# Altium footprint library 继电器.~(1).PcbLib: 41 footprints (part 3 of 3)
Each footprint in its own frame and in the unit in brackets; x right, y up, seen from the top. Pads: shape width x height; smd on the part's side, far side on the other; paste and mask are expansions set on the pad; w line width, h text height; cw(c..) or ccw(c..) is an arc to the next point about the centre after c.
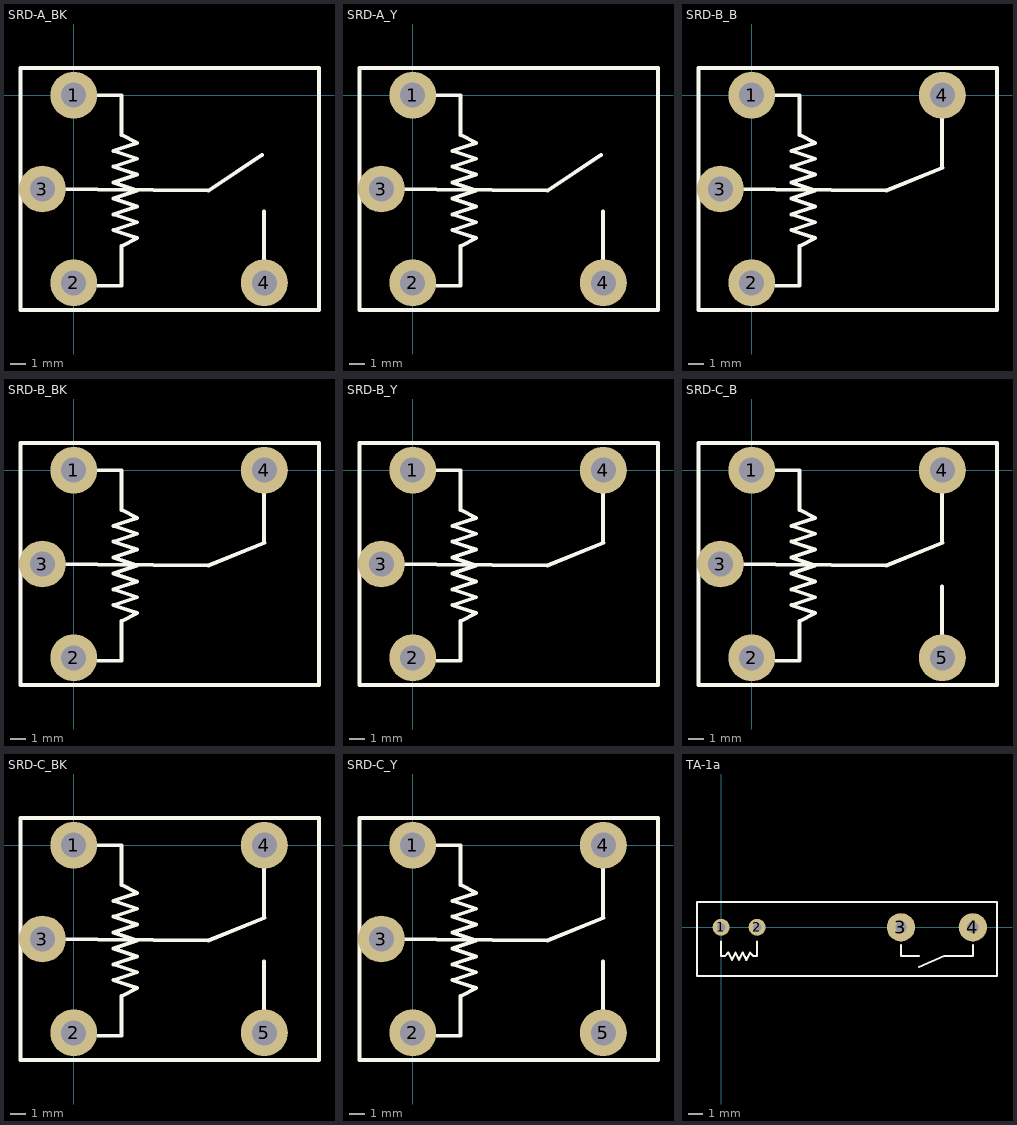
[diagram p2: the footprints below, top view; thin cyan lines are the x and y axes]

## SRD-A_BK [mm] "单刀单投/常开"
pads (4):
  round 3 hole 1.6: 1(0,0) 2(0,-12) 3(-2,-6) 4(12.2,-12)
Top Overlay:
  lines w0.254: -2,-6 8.636,-6.096 12.065,-3.81 ; 1.524,-12.192 3.048,-12.192 3.048,-10.668 3.048,-9.652 4.064,-9.144 2.54,-8.636 4.064,-8.128 2.54,-7.62 4.064,-7.112 2.54,-6.604 4.064,-6.096 2.54,-5.588 4.064,-5.08 2.54,-4.572 4.064,-4.064 2.54,-3.556 4.064,-3.048 3.048,-2.54 3.048,0 1.524,0 ; 12.192,-10.668 12.192,-8.636 ; 12.192,-9.144 12.192,-7.429 ; -3.4,-13.75 15.7,-13.75 15.7,1.75 -3.4,1.75 -3.4,-13.75
3D body: height 15.6, standoff -3.4, extent -3.4,-13.75 15.7,1.75

## SRD-A_Y [mm] "单刀单投/常开"
pads (4):
  round 3 hole 1.6: 1(0,0) 2(0,-12) 3(-2,-6) 4(12.2,-12)
Top Overlay:
  lines w0.254: -2,-6 8.636,-6.096 12.065,-3.81 ; 1.524,-12.192 3.048,-12.192 3.048,-10.668 3.048,-9.652 4.064,-9.144 2.54,-8.636 4.064,-8.128 2.54,-7.62 4.064,-7.112 2.54,-6.604 4.064,-6.096 2.54,-5.588 4.064,-5.08 2.54,-4.572 4.064,-4.064 2.54,-3.556 4.064,-3.048 3.048,-2.54 3.048,0 1.524,0 ; 12.192,-10.668 12.192,-8.636 ; 12.192,-9.144 12.192,-7.429 ; -3.4,-13.75 15.7,-13.75 15.7,1.75 -3.4,1.75 -3.4,-13.75
3D body: height 15.6, standoff -3.4, extent -3.4,-13.75 15.7,1.75

## SRD-B_B [mm] "单刀单投/常闭"
pads (4):
  round 3 hole 1.6: 1(0,0) 2(0,-12) 3(-2,-6) 4(12.2,0)
Top Overlay:
  lines w0.254: -2,-6 8.636,-6.096 12.22,-4.64 ; 1.524,-12.192 3.048,-12.192 3.048,-10.668 3.048,-9.652 4.064,-9.144 2.54,-8.636 4.064,-8.128 2.54,-7.62 4.064,-7.112 2.54,-6.604 4.064,-6.096 2.54,-5.588 4.064,-5.08 2.54,-4.572 4.064,-4.064 2.54,-3.556 4.064,-3.048 3.048,-2.54 3.048,0 1.524,0 ; 12.192,-4.572 12.192,-1.524 ; -3.4,-13.75 15.7,-13.75 15.7,1.75 -3.4,1.75 -3.4,-13.75
3D body: height 15.6, standoff -3.4, extent -3.4,-13.75 15.7,1.75

## SRD-B_BK [mm] "单刀单投/常闭"
pads (4):
  round 3 hole 1.6: 1(0,0) 2(0,-12) 3(-2,-6) 4(12.2,0)
Top Overlay:
  lines w0.254: -2,-6 8.636,-6.096 12.22,-4.64 ; 1.524,-12.192 3.048,-12.192 3.048,-10.668 3.048,-9.652 4.064,-9.144 2.54,-8.636 4.064,-8.128 2.54,-7.62 4.064,-7.112 2.54,-6.604 4.064,-6.096 2.54,-5.588 4.064,-5.08 2.54,-4.572 4.064,-4.064 2.54,-3.556 4.064,-3.048 3.048,-2.54 3.048,0 1.524,0 ; 12.192,-4.572 12.192,-1.524 ; -3.4,-13.75 -3.4,1.75 15.7,1.75 15.7,-13.75 -3.4,-13.75
3D body: height 15.6, standoff -3.4, extent -3.4,-13.75 15.7,1.75

## SRD-B_Y [mm] "单刀单投/常闭"
pads (4):
  round 3 hole 1.6: 1(0,0) 2(0,-12) 3(-2,-6) 4(12.2,0)
Top Overlay:
  lines w0.254: -2,-6 8.636,-6.096 12.22,-4.64 ; 1.524,-12.192 3.048,-12.192 3.048,-10.668 3.048,-9.652 4.064,-9.144 2.54,-8.636 4.064,-8.128 2.54,-7.62 4.064,-7.112 2.54,-6.604 4.064,-6.096 2.54,-5.588 4.064,-5.08 2.54,-4.572 4.064,-4.064 2.54,-3.556 4.064,-3.048 3.048,-2.54 3.048,0 1.524,0 ; 12.192,-4.572 12.192,-1.524 ; -3.4,-13.75 15.7,-13.75 15.7,1.75 -3.4,1.75 -3.4,-13.75
3D body: height 15.6, standoff -3.4, extent -3.4,-13.75 15.7,1.75

## SRD-C_B [mm] "单刀双投"
pads (5):
  round 3 hole 1.6: 1(0,0) 2(0,-12) 3(-2,-6) 4(12.2,0) 5(12.2,-12)
Top Overlay:
  lines w0.254: -2,-6 8.636,-6.096 12.22,-4.64 ; 1.524,-12.192 3.048,-12.192 3.048,-10.668 3.048,-9.652 4.064,-9.144 2.54,-8.636 4.064,-8.128 2.54,-7.62 4.064,-7.112 2.54,-6.604 4.064,-6.096 2.54,-5.588 4.064,-5.08 2.54,-4.572 4.064,-4.064 2.54,-3.556 4.064,-3.048 3.048,-2.54 3.048,0 1.524,0 ; 12.192,-10.668 12.192,-8.636 ; 12.192,-9.144 12.192,-7.429 ; 12.192,-4.572 12.192,-1.524 ; -3.4,-13.75 -3.4,1.75 15.7,1.75 15.7,-13.75 -3.4,-13.75
3D body: height 15.6, standoff -3.4, extent -3.4,-13.75 15.7,1.75

## SRD-C_BK [mm] "单刀双投"
pads (5):
  round 3 hole 1.6: 1(0,0) 2(0,-12) 3(-2,-6) 4(12.2,0) 5(12.2,-12)
Top Overlay:
  lines w0.254: -2,-6 8.636,-6.096 12.22,-4.64 ; 1.524,-12.192 3.048,-12.192 3.048,-10.668 3.048,-9.652 4.064,-9.144 2.54,-8.636 4.064,-8.128 2.54,-7.62 4.064,-7.112 2.54,-6.604 4.064,-6.096 2.54,-5.588 4.064,-5.08 2.54,-4.572 4.064,-4.064 2.54,-3.556 4.064,-3.048 3.048,-2.54 3.048,0 1.524,0 ; 12.192,-10.668 12.192,-8.636 ; 12.192,-9.144 12.192,-7.429 ; 12.192,-4.572 12.192,-1.524 ; -3.4,-13.75 15.7,-13.75 15.7,1.75 -3.4,1.75 -3.4,-13.75
3D body: height 15.6, standoff -3.4, extent -3.4,-13.75 15.7,1.75

## SRD-C_Y [mm] "单刀双投"
pads (5):
  round 3 hole 1.6: 1(0,0) 2(0,-12) 3(-2,-6) 4(12.2,0) 5(12.2,-12)
Top Overlay:
  lines w0.254: -2,-6 8.636,-6.096 12.22,-4.64 ; 1.524,-12.192 3.048,-12.192 3.048,-10.668 3.048,-9.652 4.064,-9.144 2.54,-8.636 4.064,-8.128 2.54,-7.62 4.064,-7.112 2.54,-6.604 4.064,-6.096 2.54,-5.588 4.064,-5.08 2.54,-4.572 4.064,-4.064 2.54,-3.556 4.064,-3.048 3.048,-2.54 3.048,0 1.524,0 ; 12.192,-10.668 12.192,-8.636 ; 12.192,-9.144 12.192,-7.429 ; 12.192,-4.572 12.192,-1.524 ; -3.4,-13.75 -3.4,1.75 15.7,1.75 15.7,-13.75 -3.4,-13.75
3D body: height 15.6, standoff -3.4, extent -3.4,-13.75 15.7,1.75

## TA-1a [mm] "微功耗超薄继电器21mm*5mm*12.5mm(长*宽*高)"
pads (4):
  round 1.2 hole 0.6: 1(0,0) 2(2.54,0)
  round 2 hole 0.8: 3(12.7,0) 4(17.78,0)
Top Overlay:
  lines w0.152: 0,-1.016 0,-2.032 0.254,-2.032 0.508,-1.778 0.762,-2.286 1.016,-1.778 1.27,-2.286 1.524,-1.778 1.778,-2.286 2.032,-1.778 2.286,-2.032 2.54,-2.032 2.54,-1.016 ; 12.7,-1.27 12.7,-2.032 13.97,-2.032 ; 13.97,-2.794 15.748,-2.032 17.78,-2.032 17.78,-1.27 ; -1.702,-3.429 19.482,-3.429 19.482,1.778 -1.702,1.778 -1.702,-3.429
3D body: height 12.55, standoff -3.45, extent -1.61,-3.33 19.39,1.67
